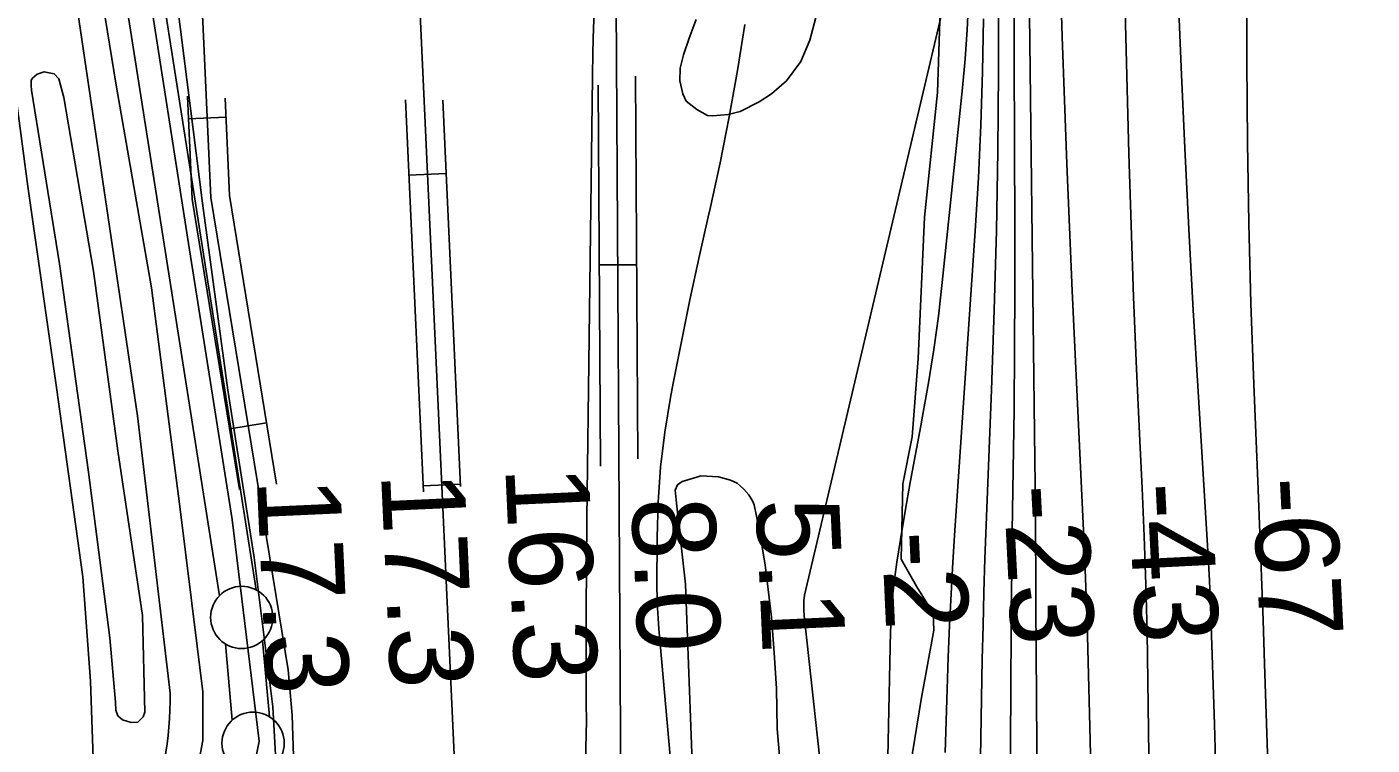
# Model space of a CAD drawing. Extents: x 3651524 to 3689615, y 505651 to 531377.
# Drawn here: x 3657229 to 3658310, y 520209 to 520786 of the extents above; entities that cross this region are included whole.
import ezdxf

# ---------------------------------------------------------------- set-up
doc = ezdxf.new("R2010")
doc.units = 0
for name, color, linetype in [('V-FLOD-BASE', 7, 'Continuous'), ('V-LEVE-TOET', 7, 'Continuous'), ('V-RAIL-TRAK', 7, 'Continuous'), ('V-RIVR-EDGE', 7, 'Continuous'), ('V-RIVR-RANG', 7, 'Continuous'), ('V-ROAD-CNTR', 7, 'Continuous'), ('V-SITE-VEGE', 7, 'Continuous'), ('V-SURV-LINE', 7, 'Continuous'), ('V-TOPO-DPTH', 7, 'Continuous'), ('V-TOPO-MAJR', 7, 'Continuous'), ('V-TOPO-MINR', 7, 'Continuous'), ('V-TOPO-WATR', 7, 'Continuous')]:
    doc.layers.add(name, color=color, linetype=linetype)

msp = doc.modelspace()

# ---------------------------------------------------------------- linework, layer by layer
at = {"layer": 'V-FLOD-BASE'}
msp.add_lwpolyline([(3657584.385, 519450.105), (3657550.192, 519549.887), (3657468.041, 519753.256), (3657400.342, 519924.757), (3657377.124, 520019.606), (3657415.694, 520212.147), (3657393.948, 520390.344), (3657358.053, 520617.393), (3657326.102, 520821.849), (3657319.309, 520862.275), (3657308.721, 521023.282), (3657309.476, 521032.043)], dxfattribs=at)
at = {"layer": 'V-LEVE-TOET'}
for points in [[(3657282.979, 520848.555), (3657300.539, 520739.603), (3657328.955, 520576.726), (3657351.829, 520400.958), (3657370.449, 520251.837), (3657370.351, 520212.868), (3657363.842, 520178.738), (3657342.304, 520095.866), (3657328.834, 520035.286), (3657326.468, 520001.672), (3657327.896, 519982.163), (3657331.103, 519963.213), (3657345.066, 519918.091), (3657382.188, 519813.516), (3657424.779, 519717.703), (3657488.83, 519566.595), (3657497.868, 519543.408), (3657533.28, 519442.406), (3657551.271, 519391.311)], [(3657587.595, 519487.643), (3657552.232, 519591.597), (3657488.265, 519747.425), (3657422.229, 519919.822), (3657400.047, 520001.105), (3657401.014, 520022.345), (3657413.255, 520113.649), (3657428.891, 520196.625), (3657426.702, 520239.766), (3657411.702, 520359.894), (3657390.458, 520494.3), (3657370.089, 520644.634), (3657349.865, 520803.233)]]:
    msp.add_lwpolyline(points, dxfattribs=at)
at = {"layer": 'V-RAIL-TRAK'}
msp.add_lwpolyline([(3657214.56, 520771.765), (3657229.676, 520658.132), (3657252.8, 520496.53), (3657273.728, 520344.415), (3657279.922, 520260.462), (3657282.686, 520183.066), (3657281.509, 520116.364), (3657270.703, 520006.143), (3657266.718, 519958.156), (3657253.099, 519855.66), (3657233.241, 519734.377), (3657211.096, 519617.269)], dxfattribs=at)
at = {"layer": 'V-RIVR-EDGE'}
msp.add_lwpolyline([(3657962.99, 520799.682), (3657961.025, 520733.651), (3657950.572, 520633.422), (3657945.489, 520519.973), (3657940.53, 520456.951), (3657933.233, 520419.149), (3657931.882, 520358.519), (3657944.434, 520336.276), (3657957.589, 520315.232), (3657958.156, 520301.423), (3657947.812, 520245.618), (3657939.277, 520192.81)], dxfattribs=at)
at = {"layer": 'V-ROAD-CNTR'}
for p, q in [((3657358.874, 520712.507), (3657388.844, 520713.866)), ((3657566.001, 520668.662), (3657536.032, 520667.284)), ((3657718.997, 520595.205), (3657688.998, 520595.027)), ((3657391.975, 520463.27), (3657421.582, 520468.11)), ((3657577.48, 520418.926), (3657547.512, 520417.548))]:
    msp.add_line(p, q, dxfattribs=at)
for points in [[(3657525.761, 521217.392), (3657602.79, 519541.672)], [(3657528.011, 519691.047), (3657422.726, 519970.25), (3657417.743, 520003.703), (3657417.126, 520046.672), (3657429.712, 520090.361), (3657440.258, 520145.555), (3657443.938, 520175.441), (3657442.27, 520233.256), (3657438.847, 520269.516), (3657376.751, 520649.38), (3657370.353, 520790.535), (3657362.637, 520921.726), (3657364.767, 520981.322)], [(3657246.233, 520957.772), (3657317.892, 520473.788), (3657343.927, 520250.844)], [(3657702.216, 520895.11), (3657706.769, 520128.333), (3657711.485, 519996.214), (3657715.08, 519872.876), (3657711.198, 519742.398), (3657691.043, 519595.941), (3657648.673, 519520.111), (3657597.244, 519484.21)], [(3657718.096, 520746.912), (3657719.923, 520439.293)], [(3657688.14, 520739.479), (3657689.958, 520433.32)], [(3657399.935, 520414.575), (3657361.806, 520647.825), (3657358.049, 520730.722)], [(3657429.645, 520418.788), (3657391.696, 520650.935), (3657388.146, 520729.253)], [(3657533.257, 520727.676), (3657547.741, 520412.578)], [(3657563.29, 520727.622), (3657577.567, 520417.042)]]:
    msp.add_lwpolyline(points, dxfattribs=at)
msp.add_arc((3657067.264, 520245.951), 276.706, 338.412978, 1.013261, dxfattribs=at)
at = {"layer": 'V-SITE-VEGE'}
for points in [[(3657863.073, 520793.898), (3657858.436, 520775.646), (3657851.123, 520758.521), (3657839.525, 520743.087), (3657827.475, 520732.511), (3657817.655, 520726.214), (3657802.418, 520718.392), (3657792.665, 520715.869), (3657780.246, 520715.011), (3657775.935, 520715.087), (3657767.393, 520720.092), (3657758.883, 520726.715), (3657756.29, 520732.691), (3657753.775, 520742.983), (3657753.958, 520753.227), (3657756.843, 520763.958), (3657761.394, 520777.362), (3657767.051, 520792.362)], [(3657763.932, 520188.417), (3657758.492, 520338.433), (3657751.512, 520401.114), (3657750.124, 520414.082), (3657751.816, 520418.366), (3657755.637, 520420.996), (3657767.565, 520424.56), (3657770.819, 520425.582), (3657784.827, 520424.793), (3657794.484, 520421.928), (3657799.835, 520419.675), (3657805.141, 520414.727), (3657809.379, 520410.338), (3657812.518, 520404.889), (3657813.548, 520402.175), (3657815.543, 520392.973), (3657818.992, 520374.576), (3657822.406, 520354.022), (3657824.749, 520334.028), (3657827.592, 520311.866), (3657829.783, 520283.246), (3657831.434, 520254.635), (3657831.944, 520222.27), (3657835.974, 520175.818)]]:
    msp.add_lwpolyline(points, dxfattribs=at)
msp.add_lwpolyline([(3657232.693, 520735.473), (3657232.222, 520739.255), (3657232.297, 520743.568), (3657233.403, 520745.168), (3657237.235, 520748.336), (3657242.664, 520750.396), (3657250.721, 520748.637), (3657254.428, 520744.795), (3657258.477, 520729.626), (3657282.434, 520590.065), (3657301.995, 520445.73), (3657321.764, 520313.257), (3657323.628, 520235.566), (3657322.481, 520231.81), (3657318.092, 520227.575), (3657312.692, 520227.128), (3657305.722, 520229.412), (3657302.005, 520232.711), (3657300.463, 520237.055), (3657300.039, 520243.533), (3657295.562, 520295.382), (3657278.498, 520428.348), (3657255.034, 520595.942)], close=True, dxfattribs=at)
at = {"layer": 'V-SURV-LINE'}
for points in [[(3657383.661, 520329.125), (3657303.162, 520841.983)], [(3657332.801, 520846.623), (3657413.3, 520333.765)], [(3657393.983, 520229.15), (3657388.438, 520290.466)], [(3657418.316, 520293.17), (3657423.861, 520231.854)]]:
    msp.add_lwpolyline(points, dxfattribs=at)
for centre in [(3657401.578, 520311.709), (3657410.721, 520210.611)]:
    msp.add_circle(centre, 25, dxfattribs=at)
at = {"layer": 'V-TOPO-DPTH'}
for points in [[(3658058.515, 520866.516), (3658061.296, 520778.455), (3658063.023, 520727.407), (3658064.904, 520676.365), (3658067.016, 520625.332), (3658069.281, 520574.305), (3658079.074, 520364.461), (3658079.699, 520350.18), (3658080.269, 520335.897), (3658080.755, 520321.611), (3658081.185, 520307.323), (3658083.457, 520223.869), (3658084.906, 520167.851)], [(3658084.906, 520167.851), (3658083.457, 520223.869), (3658081.185, 520307.323), (3658080.755, 520321.611), (3658080.269, 520335.897), (3658079.699, 520350.18), (3658079.074, 520364.461), (3658069.281, 520574.305), (3658067.016, 520625.332), (3658064.904, 520676.365), (3658063.023, 520727.407), (3658061.296, 520778.455), (3658058.515, 520866.516)], [(3658034.348, 520841.276), (3658039.068, 520460.062), (3658039.304, 520439.045), (3658039.506, 520418.029), (3658039.658, 520397.012), (3658039.778, 520375.994), (3658039.913, 520345.856), (3658039.942, 520339.908), (3658039.974, 520333.959), (3658040.011, 520328.01), (3658040.052, 520322.062), (3658042.469, 519984.086), (3658043.659, 519859.422), (3658045.248, 519734.764), (3658047.434, 519610.115), (3658050.019, 519485.472), (3658054.282, 519301.199), (3658055.899, 519268.795), (3658058.661, 519236.519), (3658063.142, 519204.437), (3658068.768, 519172.483), (3658082.536, 519104.913), (3658096.735, 519039.476)], [(3658096.735, 519039.476), (3658082.536, 519104.913), (3658068.768, 519172.483), (3658063.142, 519204.437), (3658058.661, 519236.519), (3658055.899, 519268.795), (3658054.282, 519301.199), (3658050.019, 519485.472), (3658047.434, 519610.115), (3658045.248, 519734.764), (3658043.659, 519859.422), (3658042.469, 519984.086), (3658040.052, 520322.062), (3658040.011, 520328.01), (3658039.974, 520333.959), (3658039.942, 520339.908), (3658039.913, 520345.856), (3658039.778, 520375.994), (3658039.658, 520397.012), (3658039.506, 520418.029), (3658039.304, 520439.045), (3658039.068, 520460.062), (3658034.348, 520841.276)], [(3657995.44, 520198.995), (3657996.969, 520278.053), (3657997.573, 520304.995), (3657998.286, 520331.935), (3657999.163, 520358.869), (3658000.15, 520385.8), (3658004.474, 520494.708), (3658006.66, 520558.656), (3658008.375, 520622.614), (3658009.385, 520686.587), (3658009.924, 520750.57), (3658010.186, 520840.421)], [(3657995.44, 520198.995), (3657996.969, 520278.053), (3657997.573, 520304.995), (3657998.286, 520331.935), (3657999.163, 520358.869), (3658000.15, 520385.8), (3658004.474, 520494.708), (3658006.66, 520558.656), (3658008.375, 520622.614), (3658009.385, 520686.587), (3658009.924, 520750.57), (3658010.186, 520840.421)], [(3658111.227, 520820.21), (3658114.863, 520684.702), (3658116.602, 520626.935), (3658118.592, 520569.177), (3658120.958, 520511.434), (3658123.576, 520453.7), (3658125.43, 520415.584), (3658127.103, 520376.909), (3658128.501, 520338.225), (3658129.486, 520299.529), (3658130.195, 520260.824), (3658132.781, 520061.642), (3658134.951, 519926.826), (3658137.677, 519792.023), (3658141.24, 519657.239), (3658145.36, 519522.468), (3658152.251, 519317.868), (3658153.831, 519285.448), (3658156.059, 519253.082), (3658159.259, 519220.798), (3658163.106, 519188.568), (3658166.222, 519165.426), (3658172.528, 519121.735), (3658179.384, 519078.136)], [(3658111.227, 520820.21), (3658114.863, 520684.702), (3658116.602, 520626.935), (3658118.592, 520569.177), (3658120.958, 520511.434), (3658123.576, 520453.7), (3658125.43, 520415.584), (3658127.103, 520376.909), (3658128.501, 520338.225), (3658129.486, 520299.529), (3658130.195, 520260.824), (3658132.781, 520061.642), (3658134.951, 519926.826), (3658137.677, 519792.023), (3658141.24, 519657.239), (3658145.36, 519522.468), (3658152.251, 519317.868), (3658153.831, 519285.448), (3658156.059, 519253.082), (3658159.259, 519220.798), (3658163.106, 519188.568), (3658166.222, 519165.426), (3658172.528, 519121.735), (3658179.384, 519078.136)], [(3657985.838, 520807.369), (3657984.801, 520784.003), (3657983.131, 520760.675), (3657981.04, 520737.371), (3657964.845, 520580.834), (3657961.699, 520553.869), (3657958.084, 520526.973), (3657953.767, 520500.18), (3657948.981, 520473.457), (3657947.495, 520465.739), (3657943.204, 520442.909), (3657939.051, 520420.054), (3657935.104, 520397.163), (3657931.295, 520374.248), (3657928.368, 520356.141), (3657926.416, 520342.234), (3657924.85, 520328.292), (3657923.864, 520314.297), (3657923.264, 520300.266), (3657919.382, 520123.535)], [(3657985.838, 520807.369), (3657984.801, 520784.003), (3657983.131, 520760.675), (3657981.04, 520737.371), (3657964.845, 520580.834), (3657961.699, 520553.869), (3657958.084, 520526.973), (3657953.767, 520500.18), (3657948.981, 520473.457), (3657947.495, 520465.739), (3657943.204, 520442.909), (3657939.051, 520420.054), (3657935.104, 520397.163), (3657931.295, 520374.248), (3657928.368, 520356.141), (3657926.416, 520342.234), (3657924.85, 520328.292), (3657923.864, 520314.297), (3657923.264, 520300.266), (3657919.382, 520123.535)], [(3657775.733, 519866.125), (3657736.904, 520302.584), (3657736.274, 520310.959), (3657735.797, 520319.34), (3657735.55, 520327.731), (3657735.456, 520336.128), (3657735.556, 520376.052), (3657736.416, 520404.34), (3657738.322, 520432.529), (3657741.797, 520460.567), (3657746.317, 520488.506), (3657748.491, 520499.914), (3657755.078, 520533.442), (3657761.916, 520566.916), (3657769.133, 520600.311), (3657776.602, 520633.653), (3657778.17, 520640.473), (3657786.166, 520677.269), (3657793.569, 520714.176), (3657800.08, 520751.251), (3657805.997, 520788.438)]]:
    msp.add_lwpolyline(points, dxfattribs=at)
at = {"layer": 'V-TOPO-MAJR'}
msp.add_lwpolyline([(3658152.363, 520863.971), (3658156.91, 520754.09), (3658159.812, 520688.901), (3658162.984, 520623.727), (3658166.564, 520558.573), (3658170.414, 520493.434), (3658178.122, 520369.584), (3658178.937, 520355.502), (3658179.669, 520341.416), (3658180.279, 520327.324), (3658180.806, 520313.228), (3658183.69, 520225.855), (3658185.214, 520168.066)], dxfattribs=at)
at = {"layer": 'V-TOPO-MINR'}
for points in [[(3658058.515, 520866.516), (3658061.296, 520778.455), (3658063.023, 520727.407), (3658064.904, 520676.365), (3658067.016, 520625.332), (3658069.281, 520574.305), (3658079.074, 520364.461), (3658079.699, 520350.18), (3658080.269, 520335.897), (3658080.755, 520321.611), (3658081.185, 520307.323), (3658083.457, 520223.869), (3658084.906, 520167.851)], [(3658034.348, 520841.276), (3658039.068, 520460.062), (3658039.304, 520439.045), (3658039.506, 520418.029), (3658039.658, 520397.012), (3658039.778, 520375.994), (3658039.913, 520345.856), (3658039.942, 520339.908), (3658039.974, 520333.959), (3658040.011, 520328.01), (3658040.052, 520322.062), (3658042.469, 519984.086), (3658043.659, 519859.422), (3658045.248, 519734.764), (3658047.434, 519610.115), (3658050.019, 519485.472), (3658054.282, 519301.199), (3658055.899, 519268.795), (3658058.661, 519236.519), (3658063.142, 519204.437), (3658068.768, 519172.483), (3658082.536, 519104.913), (3658096.735, 519039.476)], [(3658010.186, 520840.421), (3658009.924, 520750.57), (3658009.385, 520686.587), (3658008.375, 520622.614), (3658006.66, 520558.656), (3658004.474, 520494.708), (3658000.15, 520385.8), (3657999.163, 520358.869), (3657998.286, 520331.935), (3657997.573, 520304.995), (3657996.969, 520278.053), (3657995.44, 520198.995)], [(3657970.789, 520825.085), (3657854.019, 520329.725), (3657853.515, 520324.976), (3657853.43, 520322.591), (3657853.52, 520317.81), (3657853.841, 520313.036), (3657854.071, 520310.653), (3657967.614, 519270.892), (3657970.931, 519246.642), (3657975.114, 519222.568), (3657980.598, 519198.756), (3657986.947, 519175.118), (3658322.306, 518049.691)], [(3658022.249, 520828.932), (3658023.097, 520624.88), (3658023.15, 520576.233), (3658023.003, 520527.587), (3658022.558, 520478.942), (3658021.914, 520430.299), (3658020.841, 520364.571), (3658020.61, 520348.793), (3658020.413, 520333.014), (3658020.27, 520317.235), (3658020.161, 520301.455), (3658019.205, 520118.237)], [(3658111.227, 520820.21), (3658114.863, 520684.702), (3658116.602, 520626.935), (3658118.592, 520569.177), (3658120.958, 520511.434), (3658123.576, 520453.7), (3658125.43, 520415.584), (3658127.103, 520376.909), (3658128.501, 520338.225), (3658129.486, 520299.529), (3658130.195, 520260.824), (3658132.781, 520061.642), (3658134.951, 519926.826), (3658137.677, 519792.023), (3658141.24, 519657.239), (3658145.36, 519522.468), (3658152.251, 519317.868), (3658153.831, 519285.448), (3658156.059, 519253.082), (3658159.259, 519220.798), (3658163.106, 519188.568), (3658166.222, 519165.426), (3658172.528, 519121.735), (3658179.384, 519078.136)], [(3658209.722, 520825.63), (3658209.779, 520758.33), (3658210.227, 520693.54), (3658211.198, 520628.761), (3658212.955, 520563.999), (3658215.235, 520499.247), (3658218.731, 520414.551), (3658220.136, 520379.541), (3658221.486, 520344.53), (3658222.754, 520309.516), (3658223.969, 520274.499), (3658232.536, 520018.859)], [(3657685.435, 520805.65), (3657684.502, 520785.831), (3657683.887, 520765.999), (3657683.483, 520746.159), (3657679.097, 520390.671), (3657678.738, 520353.622), (3657678.511, 520316.572), (3657678.481, 520279.522), (3657678.582, 520242.471), (3657678.657, 520228.651), (3657677.737, 520184.785), (3657675.283, 520141.046), (3657670.531, 520097.497), (3657664.245, 520054.074), (3657657.715, 520016.061)], [(3657805.997, 520788.438), (3657800.08, 520751.251), (3657793.569, 520714.176), (3657786.166, 520677.269), (3657778.17, 520640.473), (3657776.602, 520633.653), (3657769.133, 520600.311), (3657761.916, 520566.916), (3657755.078, 520533.442), (3657748.491, 520499.914), (3657746.317, 520488.506), (3657741.797, 520460.567), (3657738.322, 520432.529), (3657736.416, 520404.34), (3657735.556, 520376.052), (3657735.456, 520336.128), (3657735.55, 520327.731), (3657735.797, 520319.34), (3657736.274, 520310.959), (3657736.904, 520302.584), (3657775.733, 519866.125)], [(3657997.856, 520792.788), (3657997.094, 520750.165), (3657995.835, 520707.562), (3657993.828, 520664.987), (3657991.324, 520622.431), (3657975.032, 520381.629), (3657973.42, 520356.145), (3657971.955, 520330.653), (3657970.714, 520305.149), (3657969.62, 520279.638), (3657968.701, 520254.118), (3657967.868, 520228.596), (3657967.163, 520203.07)]]:
    msp.add_lwpolyline(points, dxfattribs=at)
at = {"layer": 'V-TOPO-WATR'}
msp.add_lwpolyline([(3657985.838, 520807.369), (3657984.801, 520784.003), (3657983.131, 520760.675), (3657981.04, 520737.371), (3657964.845, 520580.834), (3657961.699, 520553.869), (3657958.084, 520526.973), (3657953.767, 520500.18), (3657948.981, 520473.457), (3657947.495, 520465.739), (3657943.204, 520442.909), (3657939.051, 520420.054), (3657935.104, 520397.163), (3657931.295, 520374.248), (3657928.368, 520356.141), (3657926.416, 520342.234), (3657924.85, 520328.292), (3657923.864, 520314.297), (3657923.264, 520300.266), (3657919.382, 520123.535)], dxfattribs=at)

# ---------------------------------------------------------------- texts
at = {"layer": 'V-RIVR-RANG'}
for s, rotation, p in [('17.3', 272.608326, (3657513.561, 520427.58)), ('16.3', 272.608326, (3657613.446, 520432.38)), ('-67', 272.892972, (3658214.077, 520423.314)), ('17.3', 272.608326, (3657413.676, 520422.78)), ('-23', 272.892972, (3658014.121, 520417.402)), ('-43', 272.892972, (3658114.166, 520419.04)), ('8.0', 272.608326, (3657714.711, 520406.877)), ('5.1', 272.608326, (3657814.835, 520406.407)), ('-2', 272.608326, (3657916.137, 520380.113))]:
    msp.add_text(s, height=67, rotation=rotation, dxfattribs=at).set_placement(p)

doc.saveas('drawing.dxf')
